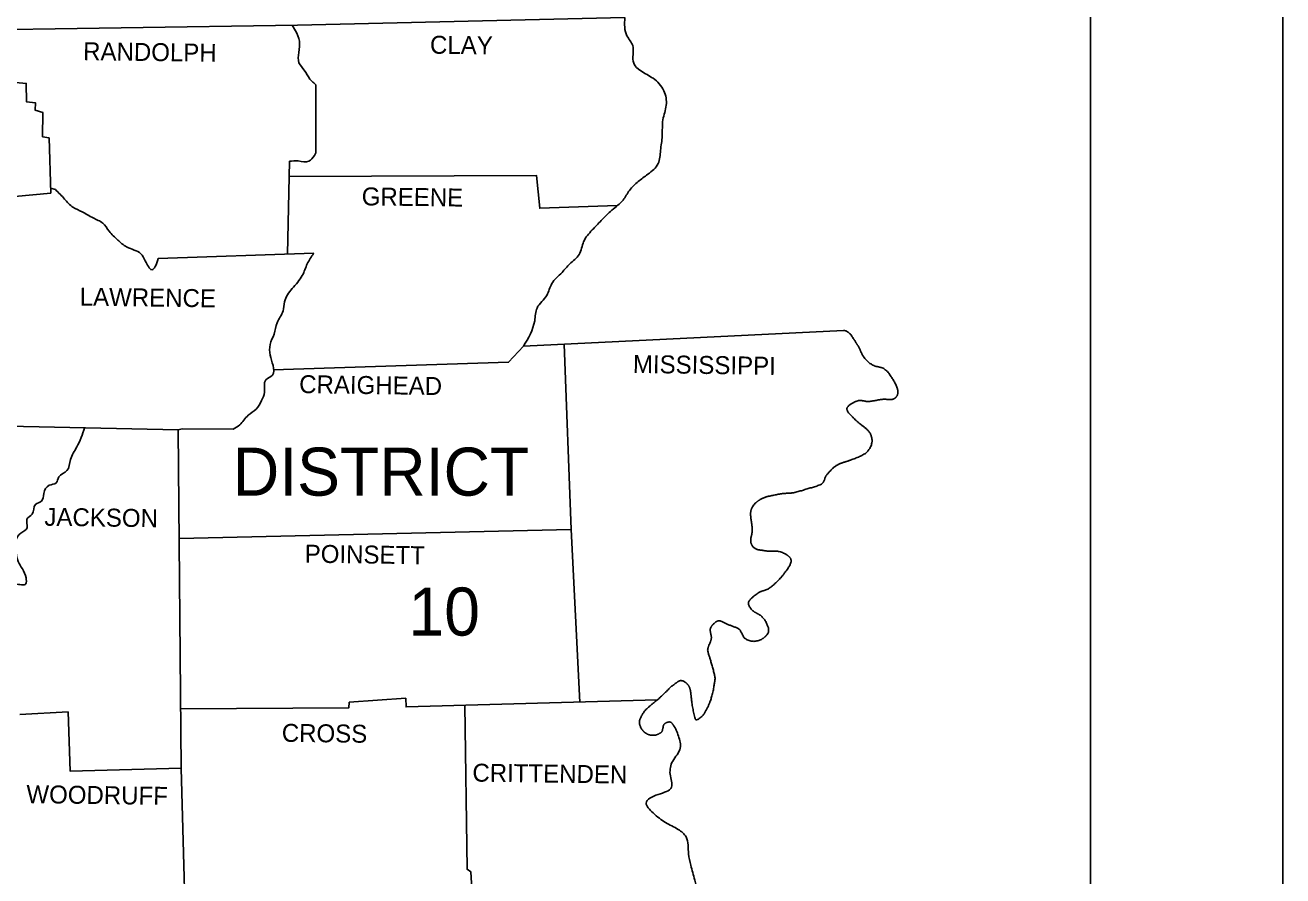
# Model space of a CAD drawing. Extents: x -0.96 to 2.36, y -0.12 to 0.92.
# Drawn here: x 1.2805 to 1.4167, y 0.727 to 0.8191 of the extents above; entities that cross this region are included whole.
import ezdxf

# ---------------------------------------------------------------- set-up
doc = ezdxf.new("R2010")
doc.units = 0
doc.layers.add('SHET_Annotations', color=7, linetype='Continuous')
doc.layers.add('SHET_Border-Lines', color=7, linetype='Continuous')

msp = doc.modelspace()

# ---------------------------------------------------------------- linework, layer by layer
at = {"layer": 'SHET_Annotations'}
for p, q in [((1.30981, 0.81849), (1.30946, 0.81908)), ((1.31178, 0.81283), (1.31202, 0.81262)), ((1.31186, 0.80498), (1.31202, 0.80525)), ((1.28383, 0.80129), (1.28329, 0.80145)), ((1.31176, 0.79437), (1.31177, 0.79439)), ((1.27998, 0.74445), (1.28519, 0.74474))]:
    msp.add_line(p, q, dxfattribs=at)
for points in [[(1.0951, 0.81784), (1.16886, 0.81779), (1.23364, 0.81792), (1.31002, 0.81908), (1.34545, 0.81991)], [(1.27561, 0.81856), (1.27545, 0.81716), (1.27636, 0.81703), (1.27628, 0.81652), (1.27734, 0.81628), (1.27742, 0.81553), (1.27794, 0.81522), (1.27807, 0.81304), (1.28066, 0.81278), (1.28069, 0.81078), (1.28165, 0.81068), (1.28162, 0.8099), (1.28245, 0.80964), (1.28243, 0.807), (1.28313, 0.80687), (1.28331, 0.8009), (1.27944, 0.80054), (1.2795, 0.79927), (1.27833, 0.79919), (1.27872, 0.77567), (1.2971, 0.77525), (1.29742, 0.73864), (1.28541, 0.73832), (1.28519, 0.74474)], [(1.31202, 0.81262), (1.31202, 0.80525)], [(1.30892, 0.79429), (1.30914, 0.80435)], [(1.3091, 0.80269), (1.33588, 0.80282), (1.33624, 0.79927), (1.3446, 0.79956)], [(1.29495, 0.79382), (1.31177, 0.79439)], [(1.33448, 0.78431), (1.36912, 0.78604)], [(1.3074, 0.78176), (1.33287, 0.78259), (1.33448, 0.78431)], [(1.33887, 0.78453), (1.33964, 0.76447), (1.34056, 0.74579)], [(1.30307, 0.77533), (1.29752, 0.77536), (1.2971, 0.77525)], [(1.33964, 0.76447), (1.2972, 0.7635)], [(1.29736, 0.74504), (1.31557, 0.74515), (1.31562, 0.74577), (1.32174, 0.74621), (1.32177, 0.74527), (1.34896, 0.74602)], [(1.32812, 0.74545), (1.32838, 0.72769), (1.32877, 0.72741), (1.32893, 0.72491)], [(1.29742, 0.73864), (1.29812, 0.71366), (1.28725, 0.71361), (1.2872, 0.7126), (1.28406, 0.71239), (1.2838, 0.70723), (1.27948, 0.7072)]]:
    msp.add_lwpolyline(points, dxfattribs=at)
for points in [[(1.34545, 0.81991), (1.34568, 0.81792), (1.3463, 0.81688), (1.34641, 0.81496), (1.34718, 0.81413), (1.34851, 0.81333), (1.34967, 0.81198), (1.34993, 0.81042), (1.34957, 0.80884), (1.34949, 0.80708), (1.34931, 0.80552), (1.34905, 0.80409), (1.34794, 0.80295), (1.3469, 0.80215), (1.34594, 0.80119), (1.34526, 0.80015), (1.34405, 0.79906), (1.34288, 0.79792), (1.34192, 0.79691), (1.34099, 0.79564), (1.34049, 0.79424), (1.33948, 0.79323), (1.33865, 0.79232), (1.33754, 0.7911), (1.33699, 0.78983), (1.33595, 0.78846), (1.33569, 0.78708), (1.33448, 0.78431)], [(1.30981, 0.81849), (1.31023, 0.81737), (1.31015, 0.81613), (1.31018, 0.81501), (1.31075, 0.81421), (1.31137, 0.81325), (1.31178, 0.81283)], [(1.31186, 0.80498), (1.31126, 0.80435), (1.3101, 0.80438), (1.30914, 0.80435)], [(1.28383, 0.80129), (1.28481, 0.80026), (1.28572, 0.79937), (1.2867, 0.79888), (1.2879, 0.79821), (1.28894, 0.79764), (1.28964, 0.79678), (1.29057, 0.79582), (1.29153, 0.79507), (1.29306, 0.79434), (1.29355, 0.79356), (1.29425, 0.7926), (1.29495, 0.79382)], [(1.31176, 0.79437), (1.31108, 0.79325), (1.31054, 0.79198), (1.30945, 0.79056), (1.30862, 0.78913), (1.30846, 0.78814), (1.30782, 0.78687), (1.30748, 0.78563), (1.30706, 0.78451), (1.30706, 0.78337), (1.30737, 0.78223), (1.3073, 0.78117), (1.3066, 0.78068), (1.30644, 0.77935), (1.30613, 0.77844), (1.30553, 0.77751), (1.30468, 0.77684), (1.30377, 0.7758), (1.30307, 0.77533)], [(1.28698, 0.77548), (1.28613, 0.77341), (1.28546, 0.77204), (1.28507, 0.77085), (1.28419, 0.77017), (1.2839, 0.76952), (1.28315, 0.76926), (1.28256, 0.76836), (1.2823, 0.76755), (1.28165, 0.76719), (1.28131, 0.76615), (1.28074, 0.76561), (1.28077, 0.7647), (1.28009, 0.76408), (1.27955, 0.76335), (1.27952, 0.76231), (1.27978, 0.76102), (1.28025, 0.76021), (1.28064, 0.75923), (1.28061, 0.75858), (1.27947, 0.75858), (1.27848, 0.75842)], [(1.35126, 0.74211), (1.35144, 0.74081), (1.35063, 0.73939), (1.35035, 0.73799), (1.3505, 0.73656), (1.34905, 0.73578), (1.34775, 0.73485), (1.34851, 0.73379), (1.34985, 0.73275), (1.35123, 0.732), (1.35208, 0.73119), (1.35234, 0.72935), (1.35258, 0.72813), (1.35302, 0.72652), (1.3532, 0.72536), (1.3524, 0.72401), (1.35144, 0.72372), (1.3504, 0.72406), (1.34921, 0.72414), (1.34825, 0.7232), (1.34757, 0.72196), (1.3469, 0.72066), (1.34638, 0.71957), (1.34589, 0.71841), (1.34488, 0.71703), (1.34366, 0.7168), (1.34218, 0.71644), (1.34132, 0.71542), (1.34145, 0.71374), (1.34228, 0.71257), (1.34293, 0.71117), (1.3434, 0.70993), (1.34314, 0.7084), (1.34252, 0.70726), (1.34171, 0.70656), (1.34132, 0.7051), (1.34075, 0.70401), (1.34018, 0.70365), (1.33909, 0.70375), (1.33792, 0.70396), (1.33691, 0.70388), (1.33593, 0.70337), (1.33497, 0.7037), (1.33398, 0.70477), (1.33318, 0.7056), (1.33225, 0.70591), (1.33129, 0.70541), (1.3311, 0.70391), (1.33155, 0.70235), (1.33199, 0.70025), (1.33157, 0.69901), (1.33142, 0.69688)]]:
    msp.add_spline(points, degree=3, dxfattribs=at)
msp.add_open_spline([(1.36912, 0.78604), (1.3693, 0.78602), (1.36947, 0.78594), (1.36962, 0.78583), (1.36978, 0.78572), (1.3699, 0.78558), (1.37001, 0.78543), (1.37012, 0.78526), (1.37023, 0.78509), (1.37034, 0.78492), (1.37039, 0.78483), (1.37044, 0.78474), (1.3705, 0.78466), (1.37055, 0.78457), (1.3706, 0.78449), (1.37065, 0.78441), (1.37072, 0.7843), (1.37079, 0.78419), (1.37085, 0.78407), (1.3709, 0.78395), (1.37095, 0.78383), (1.371, 0.78371), (1.37106, 0.7836), (1.37111, 0.78348), (1.37117, 0.78336), (1.37122, 0.78325), (1.3713, 0.78314), (1.37138, 0.78304), (1.37165, 0.78271), (1.37197, 0.78246), (1.37234, 0.78226), (1.37243, 0.78221), (1.37252, 0.78217), (1.37262, 0.78214), (1.37273, 0.78212), (1.37283, 0.7821), (1.37293, 0.78208), (1.37303, 0.78206), (1.37313, 0.78203), (1.37323, 0.78201), (1.37333, 0.78198), (1.37342, 0.78193), (1.37351, 0.78187), (1.37388, 0.78158), (1.37414, 0.78122), (1.37439, 0.78083), (1.37463, 0.78046), (1.37482, 0.78009), (1.37496, 0.77966), (1.37499, 0.77958), (1.375, 0.77949), (1.375, 0.77941), (1.375, 0.77932), (1.37499, 0.77922), (1.37497, 0.77913), (1.37494, 0.77904), (1.37491, 0.77896), (1.37485, 0.77888), (1.37483, 0.77884), (1.3748, 0.7788), (1.37476, 0.77877), (1.37474, 0.77875), (1.37473, 0.77874), (1.37471, 0.77872), (1.37469, 0.7787), (1.37467, 0.77869), (1.37465, 0.77868), (1.37455, 0.77862), (1.37444, 0.77857), (1.37432, 0.77856), (1.37422, 0.77855), (1.37411, 0.77854), (1.374, 0.77855), (1.37389, 0.77856), (1.37378, 0.77857), (1.37367, 0.77858), (1.37362, 0.77858), (1.37357, 0.77859), (1.37351, 0.77859), (1.37346, 0.77859), (1.3734, 0.77858), (1.37335, 0.77857), (1.37312, 0.77854), (1.37288, 0.7785), (1.37265, 0.77846), (1.37242, 0.77842), (1.37218, 0.77838), (1.37195, 0.77834), (1.37184, 0.77832), (1.37173, 0.77833), (1.37162, 0.77834), (1.3715, 0.77836), (1.37139, 0.77839), (1.37128, 0.7784), (1.37117, 0.77842), (1.37105, 0.77844), (1.37094, 0.77844), (1.37088, 0.77845), (1.37083, 0.77844), (1.37077, 0.77843), (1.37071, 0.77843), (1.37066, 0.77841), (1.3706, 0.77839), (1.37047, 0.77835), (1.37034, 0.77829), (1.37022, 0.77823), (1.37008, 0.77816), (1.36996, 0.77809), (1.36984, 0.77801), (1.36973, 0.77794), (1.36964, 0.77786), (1.36956, 0.77775), (1.36953, 0.77771), (1.36951, 0.77767), (1.36949, 0.77762), (1.36949, 0.7776), (1.36948, 0.77758), (1.36948, 0.77755), (1.36948, 0.77753), (1.36948, 0.77751), (1.36949, 0.77749), (1.36951, 0.77738), (1.36956, 0.77728), (1.36962, 0.77718), (1.3697, 0.77707), (1.36978, 0.77697), (1.36988, 0.77687), (1.37008, 0.77667), (1.37029, 0.77646), (1.3705, 0.77627), (1.37061, 0.77617), (1.37071, 0.77607), (1.37083, 0.77597), (1.37094, 0.77588), (1.37105, 0.7758), (1.37117, 0.77571), (1.37128, 0.77562), (1.37139, 0.77553), (1.3715, 0.77544), (1.37162, 0.77535), (1.37172, 0.77524), (1.37182, 0.77513), (1.3719, 0.77504), (1.37196, 0.77494), (1.37202, 0.77484), (1.37207, 0.77474), (1.37211, 0.77463), (1.37214, 0.77452), (1.37217, 0.77441), (1.37219, 0.7743), (1.3722, 0.77419), (1.37221, 0.77409), (1.3722, 0.77398), (1.37218, 0.77388), (1.37214, 0.77365), (1.37205, 0.77344), (1.37194, 0.77323), (1.37187, 0.77312), (1.3718, 0.77302), (1.37172, 0.77293), (1.37163, 0.77284), (1.37154, 0.77275), (1.37143, 0.77269), (1.3712, 0.77255), (1.37097, 0.77242), (1.37073, 0.77232), (1.37049, 0.77222), (1.37025, 0.77213), (1.37001, 0.77204), (1.36988, 0.77199), (1.36976, 0.77195), (1.36964, 0.77191), (1.36952, 0.77187), (1.3694, 0.77183), (1.36928, 0.77179), (1.36915, 0.77175), (1.36903, 0.77171), (1.36891, 0.77167), (1.36879, 0.77163), (1.36867, 0.77158), (1.36855, 0.77152), (1.36843, 0.77146), (1.36831, 0.77139), (1.3682, 0.7713), (1.36808, 0.77122), (1.36798, 0.77113), (1.36788, 0.77103), (1.36778, 0.77093), (1.36768, 0.77082), (1.36759, 0.77072), (1.36749, 0.77062), (1.3674, 0.77051), (1.36731, 0.77041), (1.36724, 0.77033), (1.36719, 0.77024), (1.36715, 0.77014), (1.3671, 0.77004), (1.36708, 0.76994), (1.36704, 0.76984), (1.367, 0.76974), (1.36696, 0.76965), (1.3669, 0.76956), (1.36685, 0.76947), (1.36677, 0.76941), (1.36669, 0.76937), (1.36646, 0.76927), (1.36623, 0.76918), (1.36599, 0.76911), (1.36576, 0.76904), (1.36552, 0.76897), (1.36529, 0.7689), (1.36504, 0.76883), (1.3648, 0.76875), (1.36456, 0.76868), (1.36432, 0.76861), (1.36408, 0.76854), (1.36383, 0.76849), (1.36373, 0.76846), (1.36362, 0.76844), (1.36351, 0.76843), (1.3634, 0.76842), (1.3633, 0.76842), (1.36319, 0.76841), (1.36308, 0.7684), (1.36297, 0.7684), (1.36286, 0.76839), (1.36275, 0.76838), (1.36264, 0.76837), (1.36254, 0.76836), (1.3623, 0.76833), (1.36206, 0.76829), (1.36182, 0.76824), (1.36158, 0.7682), (1.36135, 0.76815), (1.36111, 0.7681), (1.36098, 0.76807), (1.36085, 0.76803), (1.36072, 0.768), (1.3606, 0.76796), (1.36048, 0.76791), (1.36036, 0.76786), (1.36023, 0.7678), (1.36011, 0.76774), (1.36, 0.76766), (1.35994, 0.76762), (1.35988, 0.76758), (1.35983, 0.76754), (1.35977, 0.7675), (1.35971, 0.76745), (1.35966, 0.7674), (1.35948, 0.76723), (1.35934, 0.76705), (1.35922, 0.76684), (1.35916, 0.76674), (1.35913, 0.76664), (1.3591, 0.76653), (1.35908, 0.76642), (1.35906, 0.76631), (1.35906, 0.7662), (1.35906, 0.76606), (1.35907, 0.76592), (1.35908, 0.76578), (1.3591, 0.76564), (1.35912, 0.7655), (1.35914, 0.76536), (1.35916, 0.76522), (1.35918, 0.76508), (1.3592, 0.76494), (1.35922, 0.7648), (1.35924, 0.76466), (1.35924, 0.76452), (1.35925, 0.76437), (1.35923, 0.76422), (1.35921, 0.76408), (1.35918, 0.76393), (1.35914, 0.76378), (1.35911, 0.76364), (1.35909, 0.76349), (1.35908, 0.76334), (1.35908, 0.76319), (1.35908, 0.76312), (1.3591, 0.76305), (1.35912, 0.76297), (1.35913, 0.76294), (1.35915, 0.7629), (1.35916, 0.76286), (1.35918, 0.76283), (1.35919, 0.76279), (1.35922, 0.76275), (1.35929, 0.76263), (1.35939, 0.76253), (1.35951, 0.76245), (1.35963, 0.76237), (1.35975, 0.76232), (1.35989, 0.76229), (1.36003, 0.76226), (1.36016, 0.76224), (1.3603, 0.76222), (1.36044, 0.7622), (1.36058, 0.76218), (1.36072, 0.76216), (1.36083, 0.76214), (1.36094, 0.76213), (1.36105, 0.76213), (1.36116, 0.76213), (1.36127, 0.76214), (1.36138, 0.76214), (1.36149, 0.76214), (1.3616, 0.76214), (1.36171, 0.76214), (1.36182, 0.76214), (1.36193, 0.76213), (1.36204, 0.76211), (1.36229, 0.76206), (1.36252, 0.76198), (1.36275, 0.76187), (1.36287, 0.76181), (1.36297, 0.76175), (1.36307, 0.76167), (1.36312, 0.76163), (1.36316, 0.76159), (1.36321, 0.76155), (1.36326, 0.7615), (1.3633, 0.76146), (1.36334, 0.76141), (1.36339, 0.76133), (1.36342, 0.76125), (1.36344, 0.76117), (1.36345, 0.76108), (1.36345, 0.76099), (1.36342, 0.7609), (1.36336, 0.76072), (1.36329, 0.76055), (1.36318, 0.76039), (1.36304, 0.76018), (1.36289, 0.75996), (1.36273, 0.75975), (1.36265, 0.75965), (1.36257, 0.75955), (1.36249, 0.75945), (1.36241, 0.75934), (1.36232, 0.75925), (1.36223, 0.75915), (1.36188, 0.75878), (1.36152, 0.75844), (1.36111, 0.75814), (1.36103, 0.75808), (1.36094, 0.75803), (1.36084, 0.75799), (1.36074, 0.75795), (1.36065, 0.75792), (1.36055, 0.75788), (1.36045, 0.75785), (1.36035, 0.75782), (1.36026, 0.75778), (1.36016, 0.75775), (1.36006, 0.7577), (1.35997, 0.75765), (1.35975, 0.75752), (1.35954, 0.75737), (1.35935, 0.75721), (1.35925, 0.75713), (1.35917, 0.75705), (1.35908, 0.75696), (1.359, 0.75687), (1.35893, 0.75678), (1.35888, 0.75669), (1.3588, 0.75655), (1.35884, 0.75635), (1.35891, 0.7562), (1.35899, 0.75603), (1.3591, 0.75586), (1.35924, 0.75573), (1.35932, 0.75566), (1.35939, 0.75559), (1.35948, 0.75554), (1.35957, 0.7555), (1.35965, 0.75545), (1.35974, 0.7554), (1.35983, 0.75536), (1.35991, 0.75531), (1.36, 0.75526), (1.36008, 0.75522), (1.36015, 0.75515), (1.36023, 0.75508), (1.36054, 0.75478), (1.36075, 0.75442), (1.3609, 0.75404), (1.36102, 0.75375), (1.36102, 0.75335), (1.36082, 0.75308), (1.36079, 0.75303), (1.36075, 0.75299), (1.36071, 0.75294), (1.36067, 0.7529), (1.36063, 0.75286), (1.36058, 0.75282), (1.3605, 0.75275), (1.36041, 0.75269), (1.36032, 0.75263), (1.36013, 0.75252), (1.35994, 0.75245), (1.35974, 0.75241), (1.35953, 0.75236), (1.35932, 0.75236), (1.35912, 0.7524), (1.3589, 0.75244), (1.3587, 0.75251), (1.35852, 0.75264), (1.35841, 0.75272), (1.35833, 0.7528), (1.35827, 0.75291), (1.35821, 0.75302), (1.35816, 0.75313), (1.3581, 0.75324), (1.35804, 0.75335), (1.35798, 0.75346), (1.35792, 0.75356), (1.35786, 0.75366), (1.35776, 0.75374), (1.35766, 0.75378), (1.35734, 0.75392), (1.357, 0.75403), (1.35668, 0.75417), (1.35638, 0.75429), (1.35609, 0.75444), (1.35579, 0.75456), (1.35571, 0.75459), (1.35561, 0.75459), (1.35553, 0.75457), (1.35544, 0.75455), (1.35535, 0.75451), (1.35527, 0.75445), (1.35518, 0.75438), (1.3551, 0.75432), (1.35502, 0.75423), (1.35499, 0.75419), (1.35495, 0.75415), (1.35491, 0.7541), (1.35488, 0.75406), (1.35484, 0.75401), (1.35481, 0.75396), (1.35474, 0.75386), (1.3547, 0.75375), (1.35469, 0.75364), (1.35469, 0.75353), (1.3547, 0.75342), (1.35472, 0.75331), (1.35474, 0.7532), (1.35477, 0.7531), (1.35479, 0.75299), (1.3548, 0.75293), (1.35481, 0.75288), (1.35481, 0.75282), (1.35482, 0.75277), (1.35482, 0.75272), (1.35481, 0.75267), (1.35478, 0.75254), (1.35475, 0.75243), (1.3547, 0.75231), (1.35466, 0.75219), (1.3546, 0.75207), (1.35455, 0.75195), (1.35451, 0.75183), (1.35447, 0.75172), (1.35444, 0.75159), (1.35441, 0.75148), (1.35441, 0.75135), (1.35444, 0.75124), (1.35454, 0.75088), (1.35466, 0.75053), (1.35476, 0.75018), (1.35489, 0.7497), (1.35503, 0.74923), (1.35515, 0.74875), (1.35523, 0.7484), (1.35518, 0.74802), (1.35512, 0.74766), (1.35503, 0.74713), (1.35492, 0.7466), (1.35476, 0.74608), (1.35471, 0.74594), (1.35466, 0.7458), (1.35461, 0.74566), (1.35455, 0.74552), (1.35449, 0.74539), (1.35442, 0.74525), (1.35436, 0.74512), (1.35428, 0.74499), (1.35421, 0.74486), (1.35414, 0.74473), (1.35406, 0.7446), (1.35398, 0.74447), (1.35385, 0.74428), (1.35369, 0.74414), (1.35349, 0.74399), (1.35341, 0.74393), (1.35332, 0.7439), (1.35323, 0.74388), (1.3532, 0.74387), (1.35316, 0.74387), (1.35313, 0.74389), (1.3531, 0.74392), (1.35308, 0.74394), (1.35307, 0.74398), (1.35298, 0.74426), (1.35291, 0.74454), (1.35286, 0.74483), (1.3528, 0.74513), (1.35274, 0.74542), (1.35271, 0.74572), (1.35268, 0.74595), (1.35265, 0.74618), (1.35262, 0.74642), (1.35261, 0.74653), (1.3526, 0.74665), (1.35258, 0.74677), (1.35257, 0.74688), (1.35255, 0.747), (1.35253, 0.74712), (1.35251, 0.7472), (1.35249, 0.74727), (1.35245, 0.74735), (1.35242, 0.74743), (1.35238, 0.7475), (1.35234, 0.74757), (1.35229, 0.74764), (1.35223, 0.7477), (1.35218, 0.74776), (1.35212, 0.74783), (1.35206, 0.74789), (1.35198, 0.74795), (1.35186, 0.74803), (1.35173, 0.74809), (1.3516, 0.7481), (1.35148, 0.74812), (1.35134, 0.74809), (1.35123, 0.74802), (1.35114, 0.74797), (1.35107, 0.74792), (1.35099, 0.74786), (1.35091, 0.7478), (1.35083, 0.74774), (1.35075, 0.74768), (1.35059, 0.74756), (1.35044, 0.74744), (1.3503, 0.7473), (1.35012, 0.74712), (1.34994, 0.74695), (1.34976, 0.74678), (1.34959, 0.7466), (1.34941, 0.74643), (1.34923, 0.74626), (1.34913, 0.74616), (1.34902, 0.74607), (1.34891, 0.74598), (1.3488, 0.74589), (1.34869, 0.7458), (1.34858, 0.74571), (1.34846, 0.74562), (1.34835, 0.74552), (1.34824, 0.74543), (1.34813, 0.74534), (1.34802, 0.74524), (1.34791, 0.74515), (1.34773, 0.74498), (1.34758, 0.74479), (1.34744, 0.74459), (1.34737, 0.74449), (1.34731, 0.74439), (1.34725, 0.74428), (1.3472, 0.74418), (1.34715, 0.74409), (1.34711, 0.74398), (1.34706, 0.74387), (1.34704, 0.74375), (1.34703, 0.74364), (1.34702, 0.74351), (1.34704, 0.74339), (1.34708, 0.74327), (1.34713, 0.74313), (1.34718, 0.74301), (1.34725, 0.74289), (1.3473, 0.74283), (1.34734, 0.74277), (1.34739, 0.74272), (1.34741, 0.74269), (1.34744, 0.74266), (1.34746, 0.74263), (1.34749, 0.74261), (1.34752, 0.74258), (1.34755, 0.74255), (1.34762, 0.74248), (1.34771, 0.74242), (1.3478, 0.74237), (1.34788, 0.74232), (1.34796, 0.74228), (1.34805, 0.74225), (1.34814, 0.74223), (1.34822, 0.74221), (1.34831, 0.7422), (1.34839, 0.74219), (1.34847, 0.74219), (1.34856, 0.74219), (1.34862, 0.74219), (1.34869, 0.7422), (1.34875, 0.74221), (1.34882, 0.74222), (1.34888, 0.74224), (1.34895, 0.74227), (1.34901, 0.7423), (1.34908, 0.74233), (1.34914, 0.74236), (1.34921, 0.74239), (1.34927, 0.74243), (1.34934, 0.74247), (1.34941, 0.74253), (1.34947, 0.74259), (1.3495, 0.74268), (1.34952, 0.74276), (1.34954, 0.74285), (1.34956, 0.74294), (1.34958, 0.74302), (1.34959, 0.74311), (1.34961, 0.7432), (1.34963, 0.74328), (1.34967, 0.74335), (1.34972, 0.74341), (1.34978, 0.74346), (1.34983, 0.7435), (1.3499, 0.74353), (1.34997, 0.74356), (1.35004, 0.74359), (1.35012, 0.74361), (1.35019, 0.74363), (1.35026, 0.74364), (1.35033, 0.74363), (1.3504, 0.74361), (1.35046, 0.74359), (1.3505, 0.74354), (1.35055, 0.74349), (1.35059, 0.74344), (1.35063, 0.74338), (1.35067, 0.74333), (1.35071, 0.74327), (1.35074, 0.74322), (1.35082, 0.7431), (1.35088, 0.74299), (1.35095, 0.74287), (1.35107, 0.74263), (1.35116, 0.74237), (1.35126, 0.74211)], degree=3, dxfattribs=at)
at = {"layer": 'SHET_Border-Lines'}
for points in [[(0, 0), (1.41666, 0), (1.41666, 0.91666), (0, 0.91666)], [(0.04167, 0.02083), (1.39583, 0.02083), (1.39583, 0.89583), (0.04167, 0.89583)]]:
    msp.add_lwpolyline(points, close=True, dxfattribs=at)

# ---------------------------------------------------------------- texts
at = {"layer": 'SHET_Annotations'}
for s, height, rotation, p in [('RANDOLPH', 0.001945, 359.2573, (1.28681, 0.8153)), ('CLAY', 0.001945, 359.3364, (1.32435, 0.816)), ('GREENE', 0.001945, 359.2711, (1.31696, 0.79958)), ('LAWRENCE', 0.001945, 359.2655, (1.28644, 0.78872)), ('MISSISSIPPI', 0.0019451, 359.2098, (1.34631, 0.78143)), ('CRAIGHEAD', 0.001945, 359.1888, (1.31019, 0.77925)), ('JACKSON', 0.001945, 359.2575, (1.28262, 0.76488)), ('POINSETT', 0.001945, 359.1979, (1.31079, 0.76089)), ('CROSS', 0.001945, 359.3097, (1.30831, 0.74149)), ('CRITTENDEN', 0.001945, 359.2782, (1.32894, 0.73718)), ('WOODRUFF', 0.001945, 359.2708, (1.28067, 0.73485))]:
    msp.add_text(s, height=height, rotation=rotation, dxfattribs=at).set_placement(p)
for s, p in [('DISTRICT', (1.30302, 0.76814)), ('10', (1.32203, 0.75299))]:
    msp.add_text(s, height=0.005203, dxfattribs=at).set_placement(p)

doc.saveas('drawing.dxf')
